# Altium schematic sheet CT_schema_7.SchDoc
size 372 x 245 mm
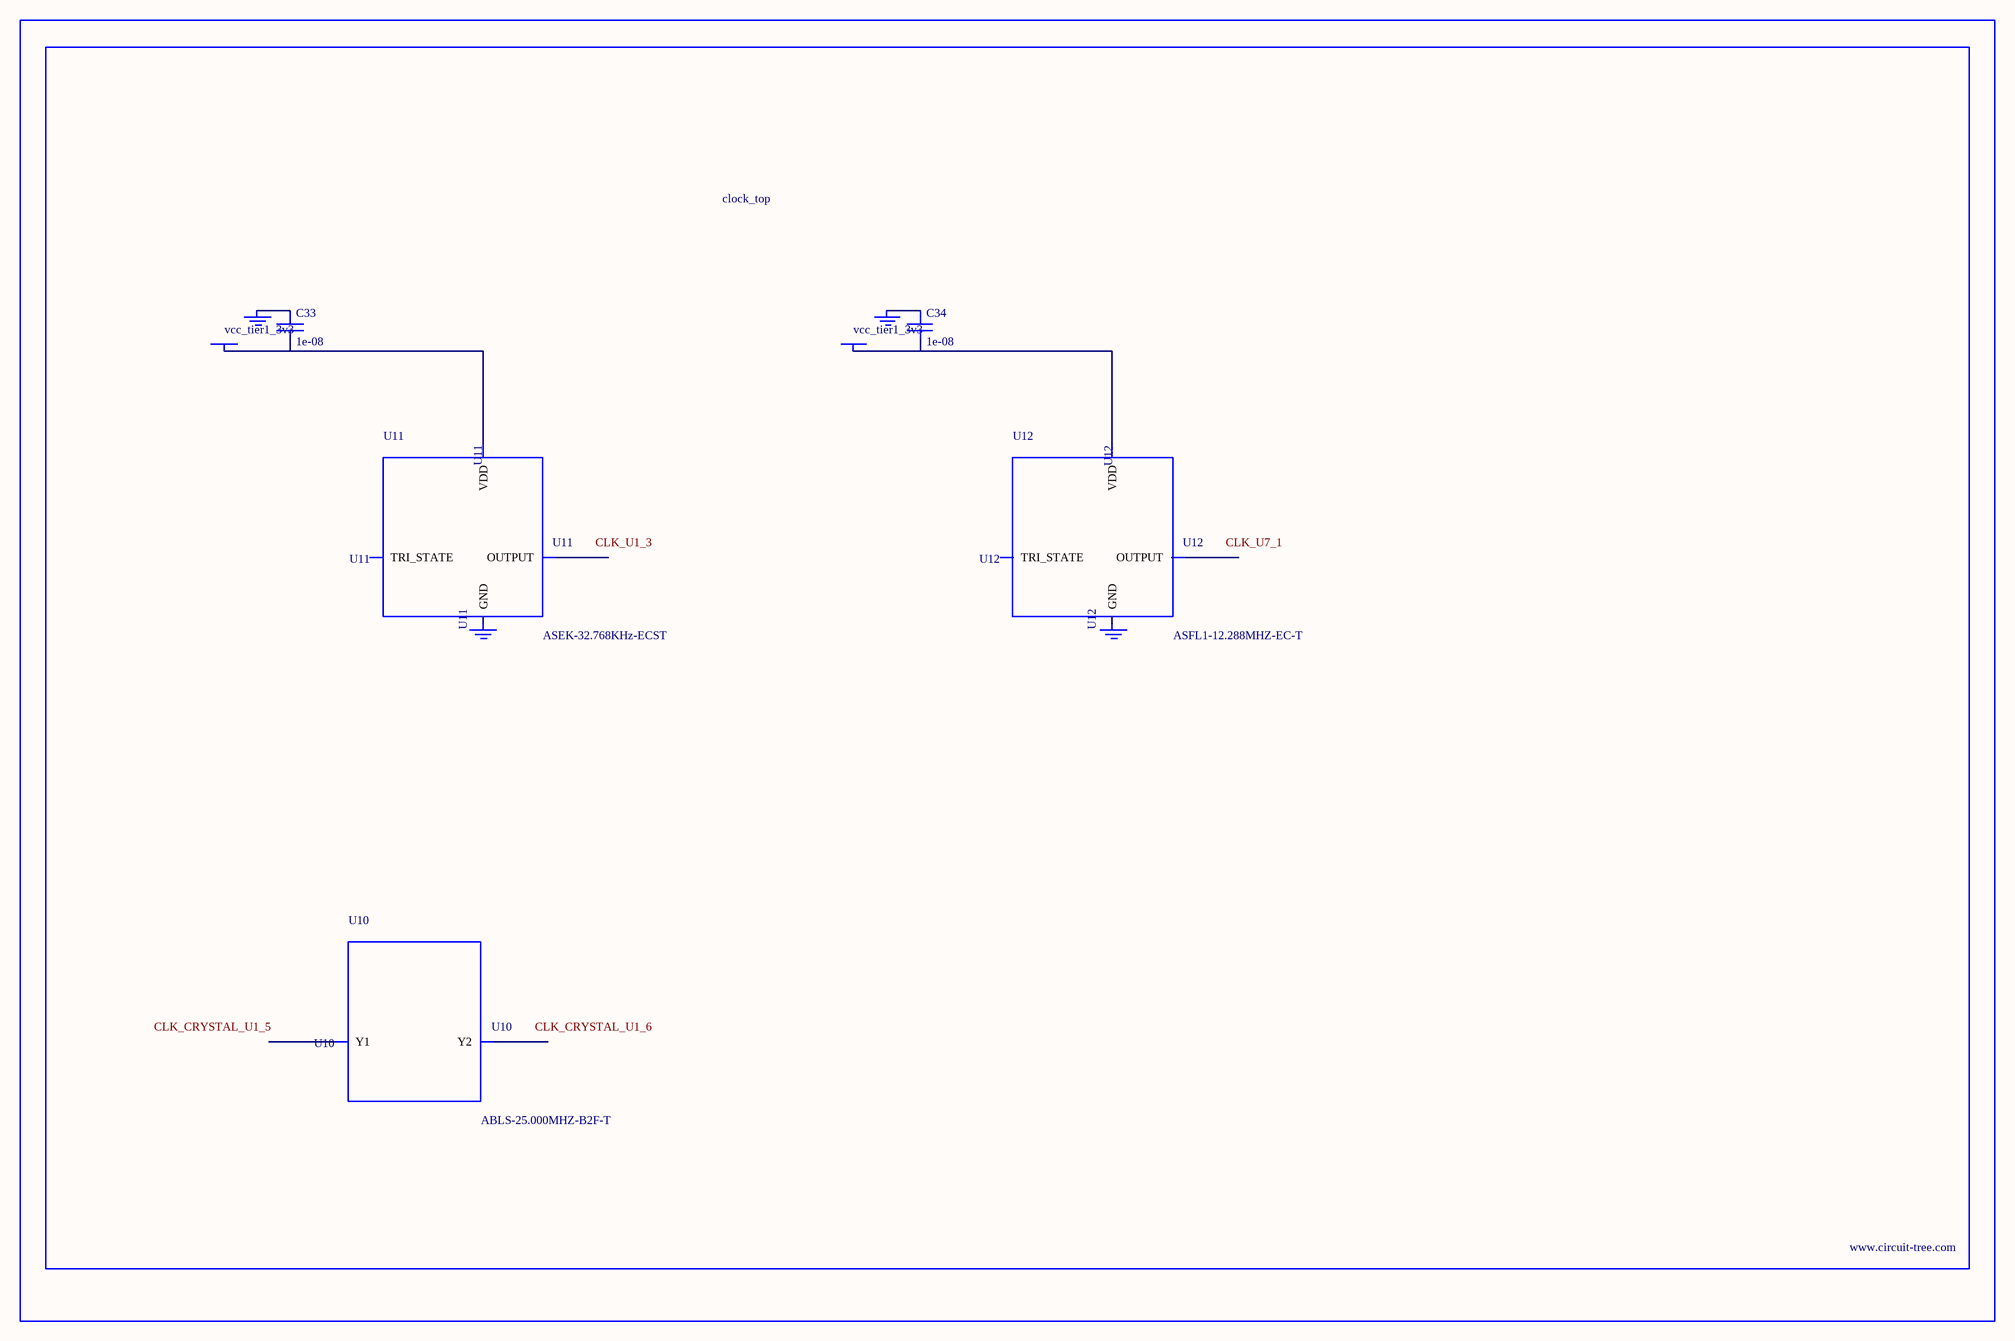
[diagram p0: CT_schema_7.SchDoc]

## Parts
BORDER6  (no value)
C33  1e-08  [C0402]
C34  1e-08  [C0402]
GND_INSTANCE_6_0  (no value)
GND_INSTANCE_6_1  (no value)
GND_INSTANCE_6_2  (no value)
GND_INSTANCE_6_3  (no value)
POWER_INSTANCE_6_0  vcc_tier1_3v3
POWER_INSTANCE_6_1  vcc_tier1_3v3
U10  ABLS-25.000MHZ-B2F-T  [ABLS-25.000MHZ-B2F-T]
U11  ASEK-32.768KHz-ECST  [ASEK]
U12  ASFL1-12.288MHZ-EC-T  [ASFL1]

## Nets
NetC33_1: C33.1 GND_INSTANCE_6_0.0(GND)
NetC33_2: C33.2 POWER_INSTANCE_6_0.0(PWR) U11.4(VDD)
NetC34_1: C34.1 GND_INSTANCE_6_2.0(GND)
NetC34_2: C34.2 POWER_INSTANCE_6_1.0(PWR) U12.4(VDD)

Not connected (* = marked no-connect by the designer): GND_INSTANCE_6_1 0(GND); GND_INSTANCE_6_3 0(GND); U10 1(Y1) 2(Y2); U11 1(TRI_STATE) 2(GND) 3(OUTPUT); U12 1(TRI_STATE) 2(GND) 3(OUTPUT)

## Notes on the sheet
- Labels drawn without touching a wire or pin: CLK_CRYSTAL_U1_5, CLK_CRYSTAL_U1_6, CLK_U1_3, CLK_U7_1

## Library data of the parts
BORDER6 = BORDER_PAGE6
C33 C34 = C0402C103K3RAC
GND_INSTANCE_6_0-GND_INSTANCE_6_3 = GND
POWER_INSTANCE_6_0 POWER_INSTANCE_6_1 = PWR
